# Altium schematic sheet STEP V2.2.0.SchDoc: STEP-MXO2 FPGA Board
size A3; Revision: V2.2; SheetNumber: 1; SheetTotal: 2; PageSetup: Record=PageOptions¦CenterHorizontal=True¦CenterVertical=True¦PrintScale=0.69¦XCorrection=1.00¦YCorrection=1.00¦PrintKind=0¦BorderSize=5000000¦LeftOffset=0¦BottomOffset=0¦Orientation=2¦PaperLength=1000¦PaperWidth=1000¦Scale=100¦PaperSource=7¦PrintQuality=-3¦MediaType=1¦DitherType=10¦PrintScaleMode=1¦PaperKind=A4¦PaperIndex=9; Function: Power,Programmer
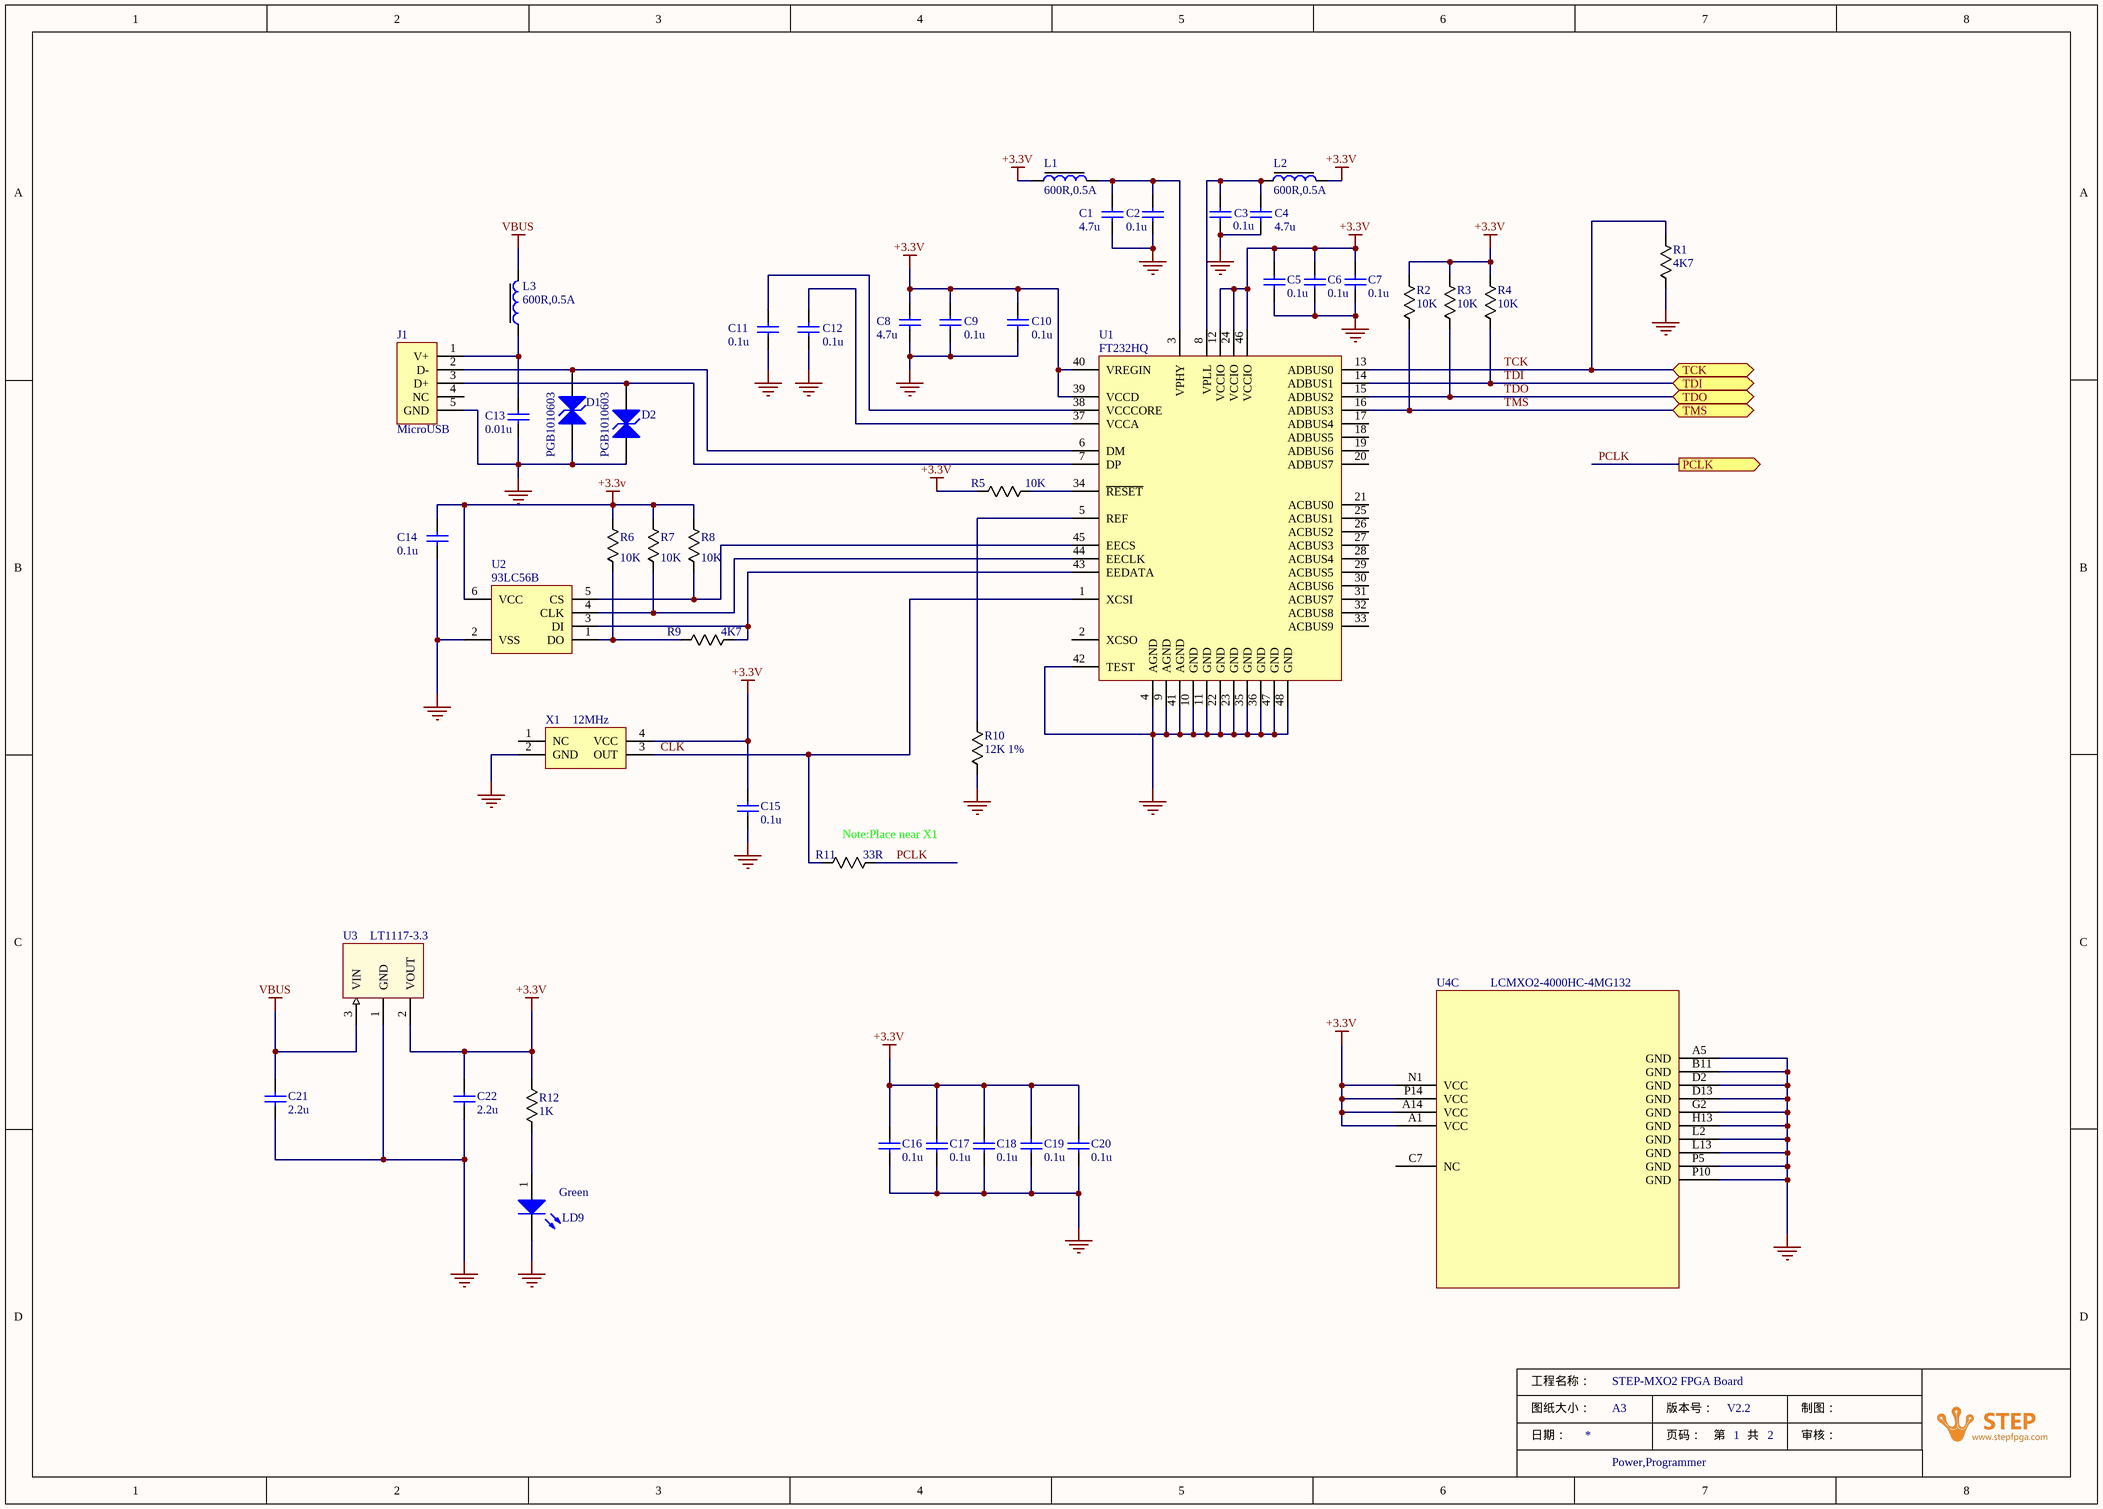
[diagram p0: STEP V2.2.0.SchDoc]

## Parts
C1  4.7u  [C0402]
C2  0.1u  [C0201]
C3  0.1u  [C0201]
C4  4.7u  [C0402]
C5  0.1u  [C0201]
C6  0.1u  [C0201]
C7  0.1u  [C0201]
C8  4.7u  [C0402]
C9  0.1u  [C0201]
C10  0.1u  [C0201]
C11  0.1u  [C0201]
C12  0.1u  [C0201]
C13  0.01u  [C0201]
C14  0.1u  [C0201]
C15  0.1u  [C0201]
C16  0.1u  [C0201]
C17  0.1u  [C0201]
C18  0.1u  [C0201]
C19  0.1u  [C0201]
C20  0.1u  [C0201]
C21  2.2u  [C0402]
C22  2.2u  [C0402]
D1  PGB1010603  [C0603]
D2  PGB1010603  [C0603]
J1  MicroUSB  [MICRO_USB_4]
L1  600R,0.5A  [L0603]
L2  600R,0.5A  [L0603]
L3  600R,0.5A  [L0603]
LD9  Green  [LED0603]
R1  4K7  [R0201]
R2  10K  [R0201]
R3  10K  [R0201]
R4  10K  [R0201]
R5  10K  [R0201]
R6  10K  [R0201]
R7  10K  [R0201]
R8  10K  [R0201]
R9  4K7  [R0201]
R10  12K 1%  [R0201]
R11  33R  [R0201]
R12  1K  [R0201]
U1  FT232HQ  [LQFP9*9_48]
U2  93LC56B  [SOT-23-6]
U3  LT1117-3.3  [SOT-89-1]
U4  LCMXO2-4000HC-4MG132  [CSBGA132]  (part C of 3)
X1  12MHz  [SMD_CLK_2.5X3.2X0.8]

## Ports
PCLK (out), TCK (bidir), TDI (bidir), TDO (bidir), TMS (bidir)

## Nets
+3.3V: C5.1(A) C6.1(A) C7.1(A) C8.1(A) C9.1(A) C10.1(A) C14.1(A) C15.1(A) C16.1(A) C17.1(A) C18.1(A) C19.1(A) C20.1(A) C22.1(A) L1.1 L2.2 R2.2 R3.2 R4.2 R5.2 R6.2 R7.2 R8.2 R12.2 U1.12(VCCIO) U1.24(VCCIO) U1.39(VCCD) U1.40(VREGIN) U1.46(VCCIO) U2.6(VCC) U3.2(VOUT) U4.A1(VCC) U4.A14(VCC) U4.N1(VCC) U4.P14(VCC) X1.4(VCC)
GND: C1.2(B) C2.2(B) C3.2(B) C4.2(B) C5.2(B) C6.2(B) C7.2(B) C8.2(B) C9.2(B) C10.2(B) C11.2(B) C12.2(B) C13.2(B) C14.2(B) C15.2(B) C16.2(B) C17.2(B) C18.2(B) C19.2(B) C20.2(B) C21.2(B) C22.2(B) D1.1(A) D2.1(A) J1.5(GND) LD9.2(K) R1.1 R10.1 U1.4(AGND) U1.9(AGND) U1.10(GND) U1.11(GND) U1.22(GND) U1.23(GND) U1.35(GND) U1.36(GND) U1.41(AGND) U1.42(TEST) U1.47(GND) U1.48(GND) U2.2(VSS) U3.1(GND) U4.A5(GND) U4.B11(GND) U4.D2(GND) U4.D13(GND) U4.G2(GND) U4.H13(GND) U4.L2(GND) U4.L13(GND) U4.P5(GND) U4.P10(GND) X1.2(GND)
VBUS: C21.1(A) L3.2 U3.3(VIN)
CLK: R11.2 U1.1(XCSI) X1.3(OUT)
PCLK: R11.1 ; port PCLK
TCK: R1.2 U1.13(ADBUS0) ; port TCK
TDI: R4.1 U1.14(ADBUS1) ; port TDI
TDO: R3.1 U1.15(ADBUS2) ; port TDO
TMS: R2.1 U1.16(ADBUS3) ; port TMS
NetC1_1: C1.1(A) C2.1(A) L1.2 U1.3(VPHY)
NetC3_1: C3.1(A) C4.1(A) L2.1 U1.8(VPLL)
NetC11_1: C11.1(A) U1.38(VCCCORE)
NetC12_1: C12.1(A) U1.37(VCCA)
NetC13_1: C13.1(A) J1.1(V+) L3.1
NetD1_2: D1.2(K) J1.2(D-) U1.6(DM)
NetD2_2: D2.2(K) J1.3(D+) U1.7(DP)
NetLD9_1: LD9.1(A) R12.1
NetR5_1: R5.1 U1.34(~{RESET})
NetR6_1: R6.1 R9.1 U2.1(DO)
NetR7_1: R7.1 U1.44(EECLK) U2.4(CLK)
NetR8_1: R8.1 U1.45(EECS) U2.5(CS)
NetR9_2: R9.2 U1.43(EEDATA) U2.3(DI)
NetR10_2: R10.2 U1.5(REF)

Not connected (* = marked no-connect by the designer): J1 4(NC); U1 2(XCSO) 17(ADBUS4) 18(ADBUS5) 19(ADBUS6) 20(ADBUS7) 21(ACBUS0) 25(ACBUS1) 26(ACBUS2) 27(ACBUS3) 28(ACBUS4) 29(ACBUS5) 30(ACBUS6) 31(ACBUS7) 32(ACBUS8) 33(ACBUS9); U4 C7(NC); X1 1(NC)

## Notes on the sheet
- (near R11) Note:Place near X1

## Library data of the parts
C1 C4 C8 = Cap_non polar: 多层陶瓷电容器MLCC - SMD/SMT 4.7uF 6.3V 10%; Manufacture: Panasonic; PartNumber: ECJ-1VB0J475K
C2 C3 C5-C7 C9-C22 = Cap_non polar: 多层陶瓷电容器MLCC - SMD/SMT 0603 xxF 50volts C0G 5%; Manufacture: Murata Electronics; PartNumber: GRM1885C1HxxxJA01D
D1 D2 = PGB1010603: ESD 抑制器 0603 24VDC .06pF; PartNumber: PGB1010603MR; Manufacture: Littelfuse
J1 = Micro USB Header
L1-L3 = BLM18AG601SN1D: EMI滤波珠子、芯片与阵列 0603 600 OHM; Manufacture: Murata
LD9 = LED: Typical INFRARED GaAs LED,1.8V,10mA,Red
R1-R10 = Res: 厚膜电阻器 - SMD xx OHM 5%; Manufacture: Yageo; PartNumber: RC0603 JR-07 xx
R11 R12 = Res: 厚膜电阻器 - SMD xx OHM 5%; PartNumber: RC0603 JR-07 xx; Manufacture: Yageo
U1 = FT232HQ: USB 接口集成电路 USB HS to UART/FIFO SPI/JTAG/I2C QFN-48; PartNumber: FT232HQ-REEL; Manufacture: FTDI
U2 = 93LC56B: 电可擦除可编程只读存储器 128x16; PartNumber: 93LC56BT-I/OT; Manufacture: Microchip Technology
U3 = LTC1117-x: LDO,5.5V to 3.3V; Part Number: LT1117CST-33#TRPBF; Manufacture: Linear Technology; FoodPrint: SOT89
U4 = LCMXO2-4000HC-4MG132: IC,LCMXO2-4000HC-4MG132 FPGA,csBGA132,4320 LUTs; Manufature: Lattice
X1 = Active Crystal: SiTime Oscillator,12MHZ SMD,2.0mm x 1.6mm; Manufacture: TXC Corporation; PartNumber: 7X-12.000MBA-T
